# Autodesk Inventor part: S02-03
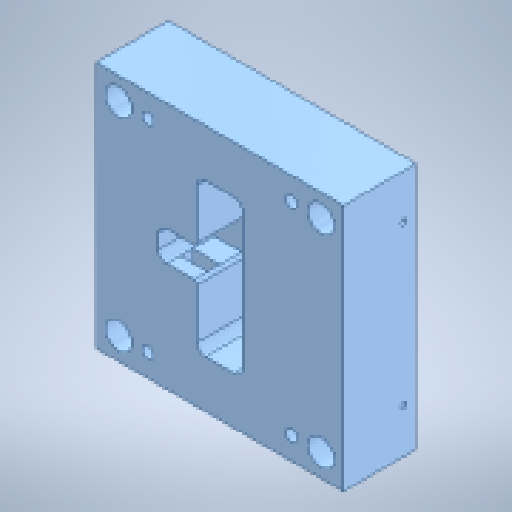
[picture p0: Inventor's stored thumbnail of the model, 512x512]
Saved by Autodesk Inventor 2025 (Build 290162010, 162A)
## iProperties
Created: 2025-04
Part Number: S02-03
Material: Všeobecné
Document SubType Name: Modeling
Designer: Patrik
Density: 1 g/cm^3
Appearance: Výchozí
Stock Number: FH 63 /396 396/115,77/IMT2/37/60/90/1730
Description: Deska horkého vtoku
Mass: 15651.8 g
Surface Area: 6783.69 cm^2
Volume: 15651.8 cm^3
User Status: 1730
Author: Patrik
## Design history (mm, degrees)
feature "Base1"
sketch "Náčrt1"
  geometry: L1 (0, -54.5)-(44, -54.5); L2 (44, -54.5)-(44, -34.5); L3 (44, -34.5)-(0, -34.5); L4 (0, -34.5)-(0, -54.5); L5 (-28, -28)-(-28, -61) reference; L6 (80, -66)-(-23, -66) reference; L7 (85, -61)-(85, -28) reference; L8 (80, -23)-(-23, -23) reference; L9 (67.5, -62)-(-10.5, -62) reference; L10 (-14, -58.5)-(-14, -30.5) reference; L11 (-10.5, -27)-(67.5, -27) reference; L12 (71, -30.5)-(71, -58.5) reference; L13 (0, -76)-(0, 0) reference; L14 (44, -76)-(44, 0) reference; A1 r 5 centre (-23, -28) between (-23, -23) and (-28, -28) reference; A2 r 5 centre (-23, -61) between (-28, -61) and (-23, -66) reference; A3 r 5 centre (80, -61) between (80, -66) and (85, -61) reference; A4 r 5 centre (80, -28) between (85, -28) and (80, -23) reference; A5 r 2.2 centre (80, -28.5) between (80, -26.3) and (80, -30.7) reference; A6 r 2.2 centre (80, -28.5) between (80, -30.7) and (80, -26.3) reference; A7 r 3.5 centre (-10.5, -58.5) between (-14, -58.5) and (-10.5, -62) reference; A8 r 3.5 centre (-10.5, -30.5) between (-10.5, -27) and (-14, -30.5) reference; A9 r 3.5 centre (67.5, -30.5) between (71, -30.5) and (67.5, -27) reference; A10 r 3.5 centre (67.5, -58.5) between (67.5, -62) and (71, -58.5) reference; A11 r 2.2 centre (80, -60.5) between (80, -58.3) and (80, -62.7) reference; A12 r 2.2 centre (80, -60.5) between (80, -62.7) and (80, -58.3) reference; A13 r 2.2 centre (-23, -28.5) between (-23, -26.3) and (-23, -30.7) reference; A14 r 2.2 centre (-23, -28.5) between (-23, -30.7) and (-23, -26.3) reference; A15 r 2.2 centre (-23, -60.5) between (-23, -58.3) and (-23, -62.7) reference; A16 r 2.2 centre (-23, -60.5) between (-23, -62.7) and (-23, -58.3) reference; 3 further points
  constraints: 8 end point, 2 collinear, 2 midpoint, 2 parallel, 1 horizontal, 1 horizontal alignment, 1 perpendicular
  dimensions: "d0" = 20 distance of L3.end L1.start
extrude "Vysunutí1" cut sketch "Náčrt1" stored distance "d2" = 10; taper "d3" = 0 deg
node "Těleso1"
node "Referenční4"
